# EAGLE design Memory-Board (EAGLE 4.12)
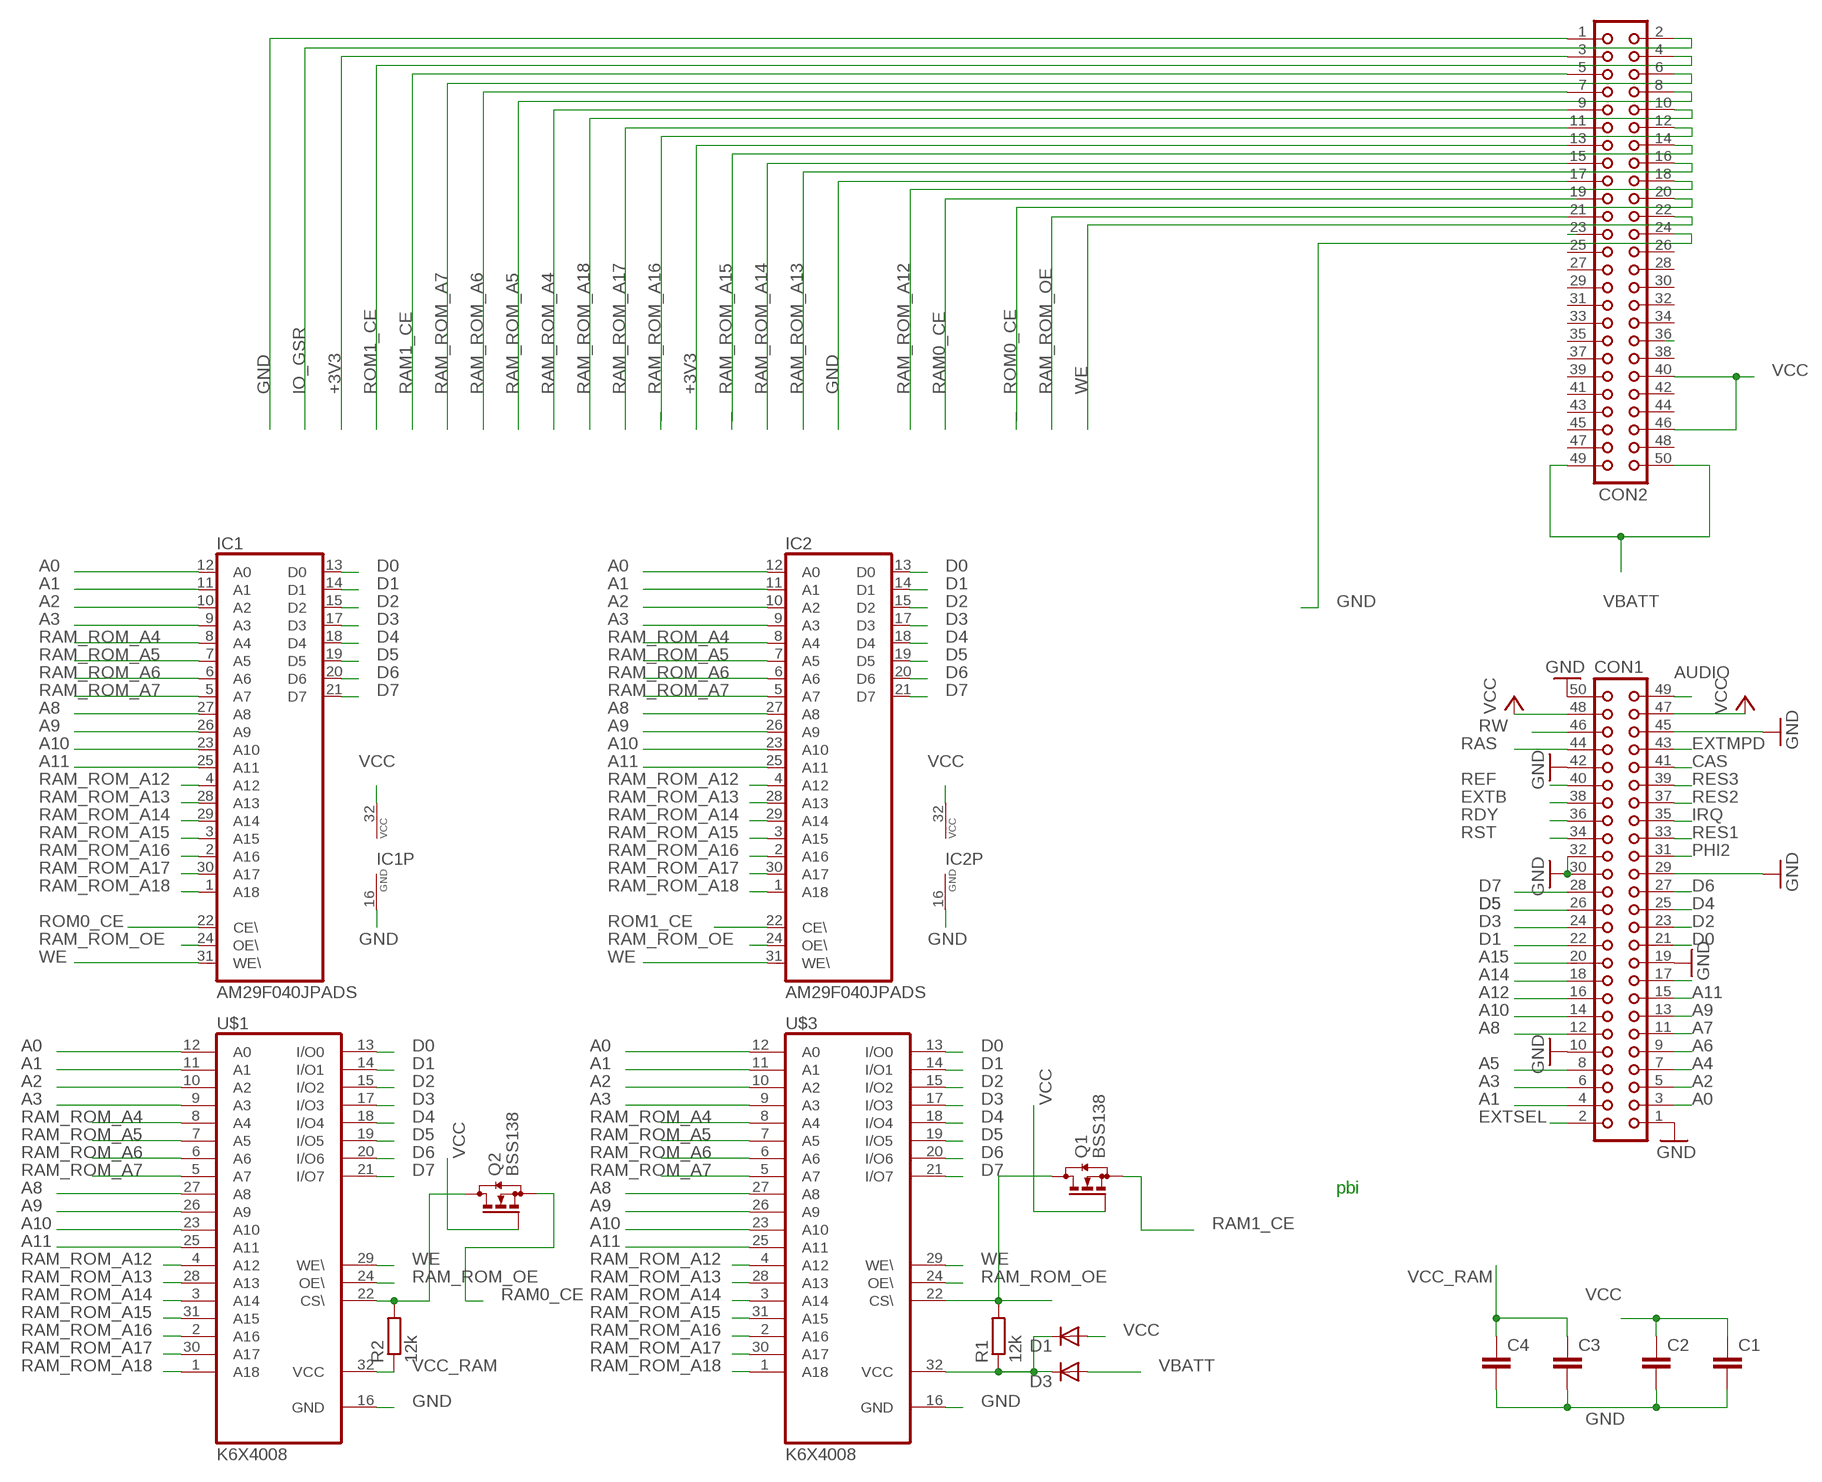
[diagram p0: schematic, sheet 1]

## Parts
C1  C-EUC1206  [C1206]
C2  C-EUC1206  [C1206]
C3  C-EUC1206  [C1206]
C4  C-EUC1206  [C1206]
CON1  CON50  [CON50]
CON2  CON50  [CON50]
D1  DIODE-DO214BA  [DO-214BA]
D3  DIODE-DO214BA  [DO-214BA]
IC1  AM29F040JPADS  [PLCC32R]
IC2  AM29F040JPADS  [PLCC32R]
Q1  BSS138  BSS123  [SOT23]
Q2  BSS138  BSS123  [SOT23]
R1  12k  R-EU_M0805  [M0805]
R2  12k  R-EU_M0805  [M0805]
U$1  K6X4008  [SOP32L]
U$3  K6X4008  [SOP32L]

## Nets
+3V3: CON2.3 CON2.13
A0: CON1.3 IC1.12(A0) IC2.12(A0) U$1.12(A0) U$3.12(A0)
A1: CON1.4 IC1.11(A1) IC2.11(A1) U$1.11(A1) U$3.11(A1)
A2: CON1.5 IC1.10(A2) IC2.10(A2) U$1.10(A2) U$3.10(A2)
A3: CON1.6 IC1.9(A3) IC2.9(A3) U$1.9(A3) U$3.9(A3)
A4: CON1.7
A5: CON1.8
A6: CON1.9
A7: CON1.11
A8: CON1.12 IC1.27(A8) IC2.27(A8) U$1.27(A8) U$3.27(A8)
A9: CON1.13 IC1.26(A9) IC2.26(A9) U$1.26(A9) U$3.26(A9)
A10: CON1.14 IC1.23(A10) IC2.23(A10) U$1.23(A10) U$3.23(A10)
A11: CON1.15 IC1.25(A11) IC2.25(A11) U$1.25(A11) U$3.25(A11)
A12: CON1.16
A13: CON1.17
A14: CON1.18
A15: CON1.20
AUDIO: CON1.49
CAS: CON1.41
D0: CON1.21 IC1.13(D0) IC2.13(D0) U$1.13(I/O0) U$3.13(I/O0)
D1: CON1.22 IC1.14(D1) IC2.14(D1) U$1.14(I/O1) U$3.14(I/O1)
D2: CON1.23 IC1.15(D2) IC2.15(D2) U$1.15(I/O2) U$3.15(I/O2)
D3: CON1.24 IC1.17(D3) IC2.17(D3) U$1.17(I/O3) U$3.17(I/O3)
D4: CON1.25 IC1.18(D4) IC2.18(D4) U$1.18(I/O4) U$3.18(I/O4)
D5: CON1.26 IC1.19(D5) IC2.19(D5) U$1.19(I/O5) U$3.19(I/O5)
D6: CON1.27 IC1.20(D6) IC2.20(D6) U$1.20(I/O6) U$3.20(I/O6)
D7: CON1.28 IC1.21(D7) IC2.21(D7) U$1.21(I/O7) U$3.21(I/O7)
DEBUG_LED8: CON2.36
EXTB: CON1.38
EXTMPD: CON1.43
EXTSEL: CON1.2
GND: C1.2 C2.2 C3.2 C4.2 CON1.1 CON1.10 CON1.19 CON1.29 CON1.30 CON1.32 CON1.42 CON1.45 CON1.50 CON2.1 CON2.17 CON2.24 IC1.16(GND) IC2.16(GND) U$1.16(GND) U$3.16(GND)
IO_GSR: CON2.2
IRQ: CON1.35
N$37: CON2.23
PHI2: CON1.31
RAM0_CE: CON2.19 Q2.2(S)
RAM0_CE1: Q2.3(D) R2.2 U$1.22(CS\)
RAM1_CE: CON2.5 Q1.2(S)
RAM1_CE1: Q1.3(D) R1.2 U$3.22(CS\)
RAM_ROM_A4: CON2.9 IC1.8(A4) IC2.8(A4) U$1.8(A4) U$3.8(A4)
RAM_ROM_A5: CON2.8 IC1.7(A5) IC2.7(A5) U$1.7(A5) U$3.7(A5)
RAM_ROM_A6: CON2.7 IC1.6(A6) IC2.6(A6) U$1.6(A6) U$3.6(A6)
RAM_ROM_A7: CON2.6 IC1.5(A7) IC2.5(A7) U$1.5(A7) U$3.5(A7)
RAM_ROM_A12: CON2.18 IC1.4(A12) IC2.4(A12) U$1.4(A12) U$3.4(A12)
RAM_ROM_A13: CON2.16 IC1.28(A13) IC2.28(A13) U$1.28(A13) U$3.28(A13)
RAM_ROM_A14: CON2.15 IC1.29(A14) IC2.29(A14) U$1.3(A14) U$3.3(A14)
RAM_ROM_A15: CON2.14 IC1.3(A15) IC2.3(A15) U$1.31(A15) U$3.31(A15)
RAM_ROM_A16: CON2.12 IC1.2(A16) IC2.2(A16) U$1.2(A16) U$3.2(A16)
RAM_ROM_A17: CON2.11 IC1.30(A17) IC2.30(A17) U$1.30(A17) U$3.30(A17)
RAM_ROM_A18: CON2.10 IC1.1(A18) IC2.1(A18) U$1.1(A18) U$3.1(A18)
RAM_ROM_OE: CON2.21 IC1.24(OE\) IC2.24(OE\) U$1.24(OE\) U$3.24(OE\)
RAS: CON1.44
RDY: CON1.36
REF: CON1.40
RES1: CON1.33
RES2: CON1.37
RES3: CON1.39
ROM0_CE: CON2.20 IC1.22(CE\)
ROM1_CE: CON2.4 IC2.22(CE\)
RST: CON1.34
RW: CON1.46
VBATT: CON2.49 CON2.50 D3.A
VCC: C1.1 C2.1 CON1.47 CON1.48 CON2.40 CON2.46 D1.A IC1.32(VCC) IC2.32(VCC) Q1.1(G) Q2.1(G)
VCC_RAM: C3.1 C4.1 D1.C D3.C R1.1 R2.1 U$1.32(VCC) U$3.32(VCC)
WE: CON2.22 IC1.31(WE\) IC2.31(WE\) U$1.29(WE\) U$3.29(WE\)
Unconnected: CON2.25 CON2.26 CON2.27 CON2.28 CON2.29 CON2.30 CON2.31 CON2.32 CON2.33 CON2.34 CON2.35 CON2.37 CON2.38 CON2.39 CON2.41 CON2.42 CON2.43 CON2.44 CON2.45 CON2.47 CON2.48

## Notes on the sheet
- pbi

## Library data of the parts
C1-C4 = rcl:C-EU: CAPACITOR, European symbol
CON1 CON2 = con-harting:CON50: CONNECTOR
D1 D3 = diode:DIODE-: DIODE
IC1 IC2 = am29-memory:AM29F040J: 4-Megabit FLASH MEMORY (512 K x 8 bit) 5 V-only
Q1 Q2 = transistor-small-signal:BSS123: N-CHANNEL MOS FET
R1 R2 = rcl:R-EU_: RESISTOR, European symbol
U$1 U$3 = memory:K6X4008

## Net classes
2 3.3: width 0.508 mm, drill 0.254 mm

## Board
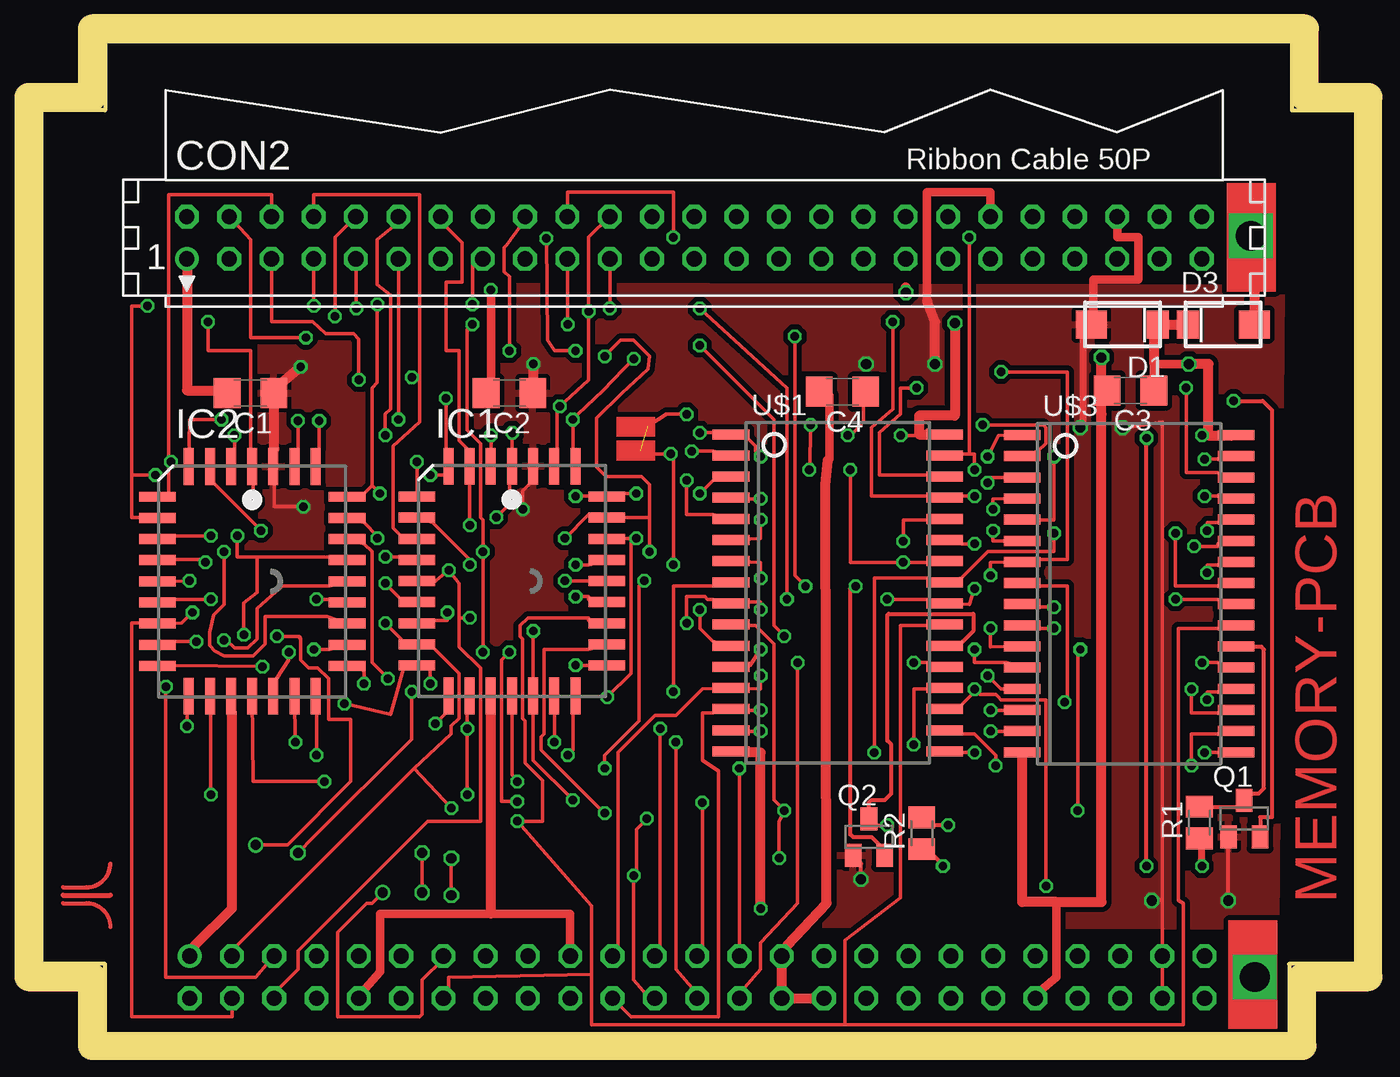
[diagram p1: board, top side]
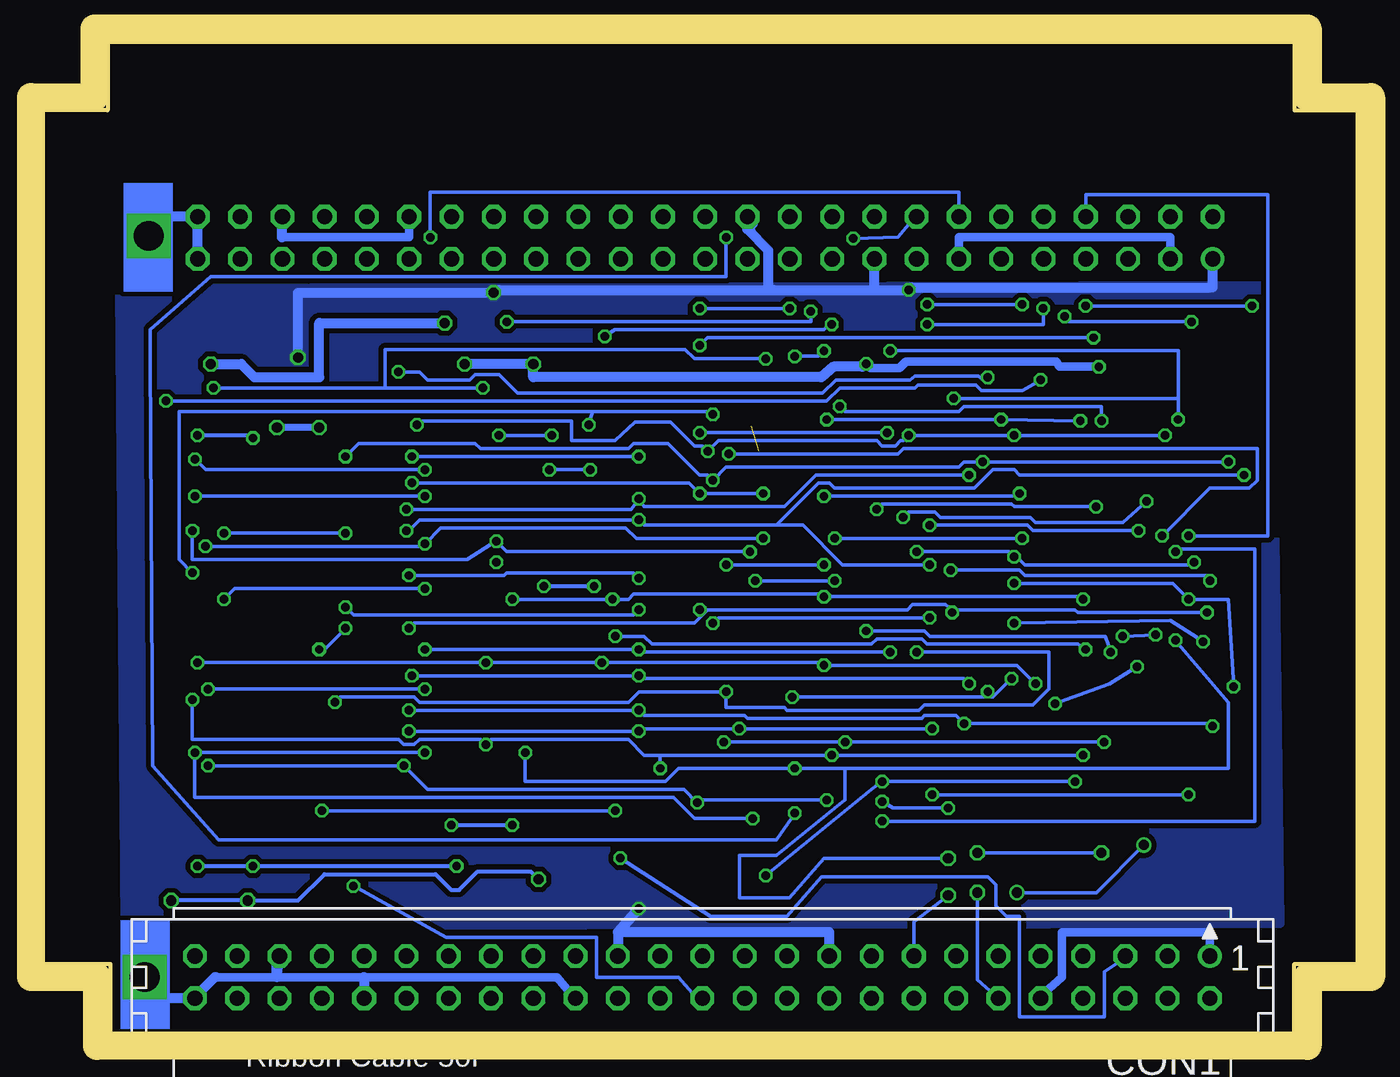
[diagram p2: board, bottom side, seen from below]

Size 79.06 x 59.69 mm. Coordinates in mm from the lower left corner, seen from the top.
Outline: 75.09,59.69 75.09,59.69
Outline: 75.09,59.69 3.81,59.69 3.81,55.56 0,55.56 0,4.29 3.81,4.29 3.81,0 74.93,0 74.93,4.29 79.06,4.29 79.06,55.56 75.09,55.56 75.09,59.69
Copper layers (1*16): Top 0.035mm / dielectric 1.5mm / Bottom 0.035mm
Design rules "ITead_rule": minimum track width 6mil, minimum drill 12mil, track to track 6mil, track to pad 6mil, pad to pad 6mil, via to via 6mil, smd to smd 0mil, copper to edge 10mil, drill to drill 10mil, minimum pad ring 10mil, minimum via ring 6mil, stop-mask expansion 2mil, vias tented up to drill 100mil, thermal gap 10mil
Milling: 15 lines

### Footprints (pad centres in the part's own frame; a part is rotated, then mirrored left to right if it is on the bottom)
C1206 = smd 1.6 x 1.8: 1 -1.4,0; 2 1.4,0
CON50 = drill 0.914 round: 1 -30.48,-1.27 | drill 0.914 octagon: 2 -30.48,1.27; 3 -27.94,-1.27; 4 -27.94,1.27; 5 -25.4,-1.27; 6 -25.4,1.27; 7 -22.86,-1.27; 8 -22.86,1.27; 9 -20.32,-1.27; 10 -20.32,1.27; 11 -17.78,-1.27; 12 -17.78,1.27; 13 -15.24,-1.27; 14 -15.24,1.27; 15 -12.7,-1.27; 16 -12.7,1.27; 17 -10.16,-1.27; 18 -10.16,1.27; 19 -7.62,-1.27; 20 -7.62,1.27; 21 -5.08,-1.27; 22 -5.08,1.27; 23 -2.54,-1.27; 24 -2.54,1.27; 25 0,-1.27; 26 0,1.27; 27 2.54,-1.27; 28 2.54,1.27; 29 5.08,-1.27; 30 5.08,1.27; 31 7.62,-1.27; 32 7.62,1.27; 33 10.16,-1.27; 34 10.16,1.27; 35 12.7,-1.27; 36 12.7,1.27; 37 15.24,-1.27; 38 15.24,1.27; 39 17.78,-1.27; 40 17.78,1.27; 41 20.32,-1.27; 42 20.32,1.27; 43 22.86,-1.27; 44 22.86,1.27; 45 25.4,-1.27; 46 25.4,1.27; 47 27.94,-1.27; 48 27.94,1.27; 49 30.48,-1.27; 50 30.48,1.27
DO-214BA = smd 1.85 x 1.68: A 1.87,0 | smd 1.32 x 1.68: C -2.12,0
PLCC32R = smd 0.6 x 2.2: 1 0,6.9; 2 -1.27,6.9; 3 -2.54,6.9; 4 -3.81,6.9; 14 -3.81,-6.9; 15 -2.54,-6.9; 16 -1.27,-6.9; 17 0,-6.9; 18 1.27,-6.9; 19 2.54,-6.9; 20 3.81,-6.9; 30 3.81,6.9; 31 2.54,6.9; 32 1.27,6.9 | smd 2.2 x 0.6: 5 -5.7,5.08; 6 -5.7,3.81; 7 -5.7,2.54; 8 -5.7,1.27; 9 -5.7,0; 10 -5.7,-1.27; 11 -5.7,-2.54; 12 -5.7,-3.81; 13 -5.7,-5.08; 21 5.7,-5.08; 22 5.7,-3.81; 23 5.7,-2.54; 24 5.7,-1.27; 25 5.7,0; 26 5.7,1.27; 27 5.7,2.54; 28 5.7,3.81; 29 5.7,5.08
SOT23 = smd 1 x 1.4: 1 -0.95,-1.1; 2 0.95,-1.1; 3 0,1.1
M0805 = smd 1.3 x 1.6: 1 -0.95,0; 2 0.95,0
SOP32L = smd 0.6 x 2.2: 1 -9.525,-6.416; 2 -8.255,-6.416; 3 -6.985,-6.416; 4 -5.715,-6.416; 5 -4.445,-6.416; 6 -3.175,-6.416; 7 -1.905,-6.416; 8 -0.635,-6.416; 9 0.635,-6.416; 10 1.905,-6.416; 11 3.175,-6.416; 12 4.445,-6.416; 13 5.715,-6.416; 14 6.985,-6.416; 15 8.255,-6.416; 16 9.525,-6.416; 17 9.525,6.416; 18 8.255,6.416; 19 6.985,6.416; 20 5.715,6.416; 21 4.445,6.416; 22 3.175,6.416; 23 1.905,6.416; 24 0.635,6.416; 25 -0.635,6.416; 26 -1.905,6.416; 27 -3.175,6.416; 28 -4.445,6.416; 29 -5.715,6.416; 30 -6.985,6.416; 31 -8.255,6.416; 32 -9.525,6.416

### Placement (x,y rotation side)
C1  12.54,38.58 180 top
C2  28.1,38.58 180 top
C3  65.41,38.73 180 top
C4  48.1,38.66 180 top
CON1  39.37,3.49 180 bottom
CON2  39.2,47.9 0 top
D1  64.93,42.7 180 top
D3  70.96,42.7 0 top
IC1  28.24,27.29 0 top
IC2  12.65,27.27 0 top
Q1  72.23,13.02 0 top
Q2  49.69,11.91 0 top
R1  69.53,12.78 90 top
R2  52.86,12.14 90 top
U$1  47.82,26.58 270 top
U$3  65.32,26.53 270 top

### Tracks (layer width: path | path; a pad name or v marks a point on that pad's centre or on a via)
+3V3
  Bottom 0.203: CON2.3 11.27,46.35 | 23.97,46.35 CON2.13
  Bottom 0.508: 11.27,46.35 11.27,47.94 23.97,47.94 23.97,46.35
A0  (via drill 0.51)
  Top 0.203: v56.04,23.18 56.04,22.38 57.94,22.38 U$3.12 | v43.18,23.18 42.55,22.22 U$1.12 | v9.29,23.65 7.94,23.65 IC2.12 | v20.64,24.76 21.59,23.81 21.59,23.65 IC1.12 23.5,23.34 25.08,21.75 25.08,19.05 24.61,18.57 24.61,18.1 22.38,16.03 | 22.38,16.03 11.75,5.4 CON1.3 | v28.1,23.02 27.62,22.54 27.62,15.72 27.62,15.56 27.62,14.05 v28.57,14.05 | 22.38,16.03 v24.61,13.65
  Bottom 0.203: v56.04,23.18 v43.18,23.18 42.86,23.02 v28.1,23.02 | v9.29,23.65 11.27,24.92 v20.64,24.76 | v28.57,14.05 27.94,13.65 v24.61,13.65
A1  (via drill 0.51)
  Top 0.203: CON1.4 11.43,1.9 11.43,1.11 5.4,1.11 5.4,24.76 5.87,24.76 IC2.11 8.41,24.76 v9.05,25.4 | v24.37,25.4 24.37,24.92 23.5,24.92 IC1.11 | v56.99,24.45 56.99,23.34 U$3.11 | v39.53,25.56 39.53,24.45 40.32,23.65 U$1.11
  Bottom 0.203: v9.05,25.4 16.83,25.4 16.99,25.56 24.13,25.56 v24.37,25.4 24.61,25.72 24.77,25.88 26.75,25.88 27.07,25.56 39.05,25.56 39.21,25.4 | v56.99,24.45 56.67,24.76 39.85,24.76 39.21,25.4 | v39.53,25.56 39.37,25.4 39.21,25.4
A2  (via drill 0.51)
  Top 0.203: v60.8,24.45 59.85,24.45 U$3.10 | v62.39,23.18 62.23,23.02 v62.23,13.49 | U$1.10 42.39,24.61 42.86,24.61 43.97,23.49 43.97,14.13 v44.61,13.49 44.29,12.86 v44.29,10.64 | v10.16,26.19 7.94,26.19 IC2.10 | v20.64,27.15 21.59,26.19 IC1.10 | v7.46,20.95 7.46,3.49 12.86,3.49 13.65,4.44 13.34,4.44 CON1.5
  Bottom 0.2: 22.22,9.52 32.23,9.52 34.29,7.14 38.89,7.14
  Bottom 0.203: v60.8,24.45 62.07,23.18 v62.39,23.18 | v44.61,13.49 v62.23,13.49 | v20.64,27.15 11.11,27.15 v10.16,26.19 7.78,26.19 v7.46,20.95 | 38.89,7.14 v44.29,10.64 | CON1.5 14.29,4.44 15.24,3.81 15.24,1.11 16.19,1.11 20.32,1.11 20.32,7.14 21.11,7.14 21.75,7.78 21.75,9.05 22.22,9.52
A3  (via drill 0.51)
  Top 0.203: v60.8,25.72 59.85,25.72 U$3.9 | v43.18,25.56 43.18,26.03 42.39,26.03 U$1.9 40.32,26.19 40.01,26.19 39.85,26.35 38.74,26.35 v38.74,24.76 | v8.89,27.3 IC2.9 | IC1.9 23.5,27.15 v24.45,27.94 25.08,27.15 25.08,25.08 | 25.08,25.08 25.08,23.34 26.35,22.07 26.35,12.86 23.18,12.86 15.4,5.08 15.4,3.97 14.29,2.86 CON1.6 | 25.08,25.08 v25.72,25.08
  Bottom 0.203: v60.8,25.72 60.33,25.24 43.5,25.24 v43.18,25.56 | v8.89,27.3 8.73,27.62 20,27.62 20.32,27.94 v24.45,27.94 | v38.74,24.76 38.42,25.08 v25.72,25.08
A8  (via drill 0.5, 0.51, 0.61)
  Top 0.2: v22.22,20.64 22.22,17.78 16.35,11.91 v15.4,10.95 | v22.86,8.57 v22.86,10.95
  Top 0.203: v56.04,29.53 55.25,29.53 U$1.27 | v69.22,29.37 70.64,29.37 70.64,29.53 U$3.27 | v20.8,21.43 19.84,22.38 19.84,29.05 19.37,29.53 IC2.27 | v33.97,20.32 35.4,21.75 35.4,29.84 34.93,29.84 | 34.93,29.84 v35.72,29.84 | 34.93,29.84 IC1.27
  Bottom 0.2: v22.22,20.64 21.91,20.32 | v22.86,10.95 v15.4,10.95 | v22.86,8.57 22.86,3.33 CON1.12 | CON1.12
  Bottom 0.203: v69.22,29.37 56.2,29.37 v56.04,29.53 55.09,30.48 43.97,30.48 43.34,29.84 v35.72,29.84 | v20.8,21.43 21.91,20.32 v33.97,20.32
A9  (via drill 0.51, 0.61)  (1 unrouted)
  Top 0.2: IC2.26 17.15,28.73
  Top 0.203: 12.94,28.73 11.75,28.73 v11.75,30 | 12.94,28.73 16.99,28.73 IC2.26 | v32.07,28.26 32.86,28.26 IC1.26 | v37.94,28.26 37.94,34.61 v37.78,34.92 36.67,34.92 35.96,35.08 | U$1.26 53.18,28.42 v51.75,28.42 48.58,28.42 v48.58,33.97 | v70.01,27.78 70.01,28.26 70.64,28.26 U$3.26 | CON1.13 24.13,4.6 22.86,3.33 22.86,1.27 22.7,1.11 17.78,1.11 17.78,6.19 19.53,7.94 19.84,7.94 v20.48,8.57 | v12.86,11.43 14.76,11.43 18.57,15.24 18.57,18.97 17.22,18.97 17.22,21.43 16.59,22.07 16.03,22.07 15.56,22.54 15.56,23.81 15.48,23.97 v14.13,23.97 | v12.14,24.05 12.14,25.96 12.94,26.59 12.94,28.73 | v38.74,37.31 37.54,37.31 36.43,36.59 | v46.2,36.67 v46.12,33.97
  Bottom 0.203: v11.75,30 8.89,32.86 6.51,32.86 6.03,33.34 6.03,35.24 27.31,35.24 27.62,34.92 v37.78,34.92 | v32.07,28.26 v37.94,28.26 38.26,28.42 | v70.01,27.78 70.8,28.57 70.8,37.46 45.96,37.46 | 45.96,37.46 38.89,37.46 v38.74,37.31 | v20.48,8.57 15.72,8.57 v12.86,11.43 | v14.13,23.97 v12.14,24.05 | v46.12,33.97 v48.58,33.97 | 45.96,37.46 v46.2,36.67
A10  (via drill 0.51)
  Top 0.203: IC2.23 17.15,25.16 13.41,25.16 13.41,23.49 12.7,22.78 10.95,22.78 10.4,23.1 10.08,23.42 10.08,24.21 10.32,25.24 10.95,25.88 v10.95,29.05 | IC1.23 32.86,24.92 32.86,25.08 29.21,25.08 28.73,24.61 28.73,23.97 28.89,23.81 28.89,19.05 29.05,18.89 29.05,16.35 30.08,15.32 30.08,12.86 v28.57,12.86 33.02,7.78 33.02,3.65 | 48.26,0.63 48.26,5.71 51.59,8.25 51.59,24.61 53.18,24.61 U$1.23 | 48.26,0.63 33.02,0.63 33.02,3.65 | 48.26,0.63 68.58,0.63 68.58,7.94 68.26,8.1 68.26,24.45 70.64,24.45 U$3.23 | 48.26,0.63 47.31,0.63 | 33.02,3.65 24.45,3.49 24.45,2.06 CON1.14
  Bottom 0.203: v10.95,29.05 10.8,29.21 6.19,29.21 6.19,12.86 v28.57,12.86
A11  (via drill 0.51, 0.61)
  Top 0.2: v24.61,10.64 v24.61,8.41
  Top 0.203: v68.1,30.16 68.1,26.99 70.64,26.99 U$3.25 | v60.8,30.16 60.8,29.05 60.17,29.05 56.83,29.05 55.25,27.46 U$1.25 53.18,27.46 50.48,27.46 50.01,27.46 v50.01,16.99 | IC2.25 17.3,26.99 14.37,26.99 14.37,26.91 12.94,25.64 12.94,23.81 12.38,23.26 11.59,23.26 11.11,23.73 v10.95,23.73 | v31.43,27.3 32.86,27.3 IC1.25 | v36.2,27.3 35.88,26.99 35.88,18.89 33.81,16.83 v33.81,16.03
  Bottom 0.2: v33.81,16.03 30.8,16.03 30.8,14.13 34.92,10.79 37.15,10.79 37.15,8.25 34.13,8.25 32.07,10.64 v24.61,10.64 24.45,10.64 | v24.61,8.41 26.67,6.83 CON1.15
  Bottom 0.203: v60.8,30.16 v68.1,30.16 | v10.95,23.73 7.78,20 7.78,16.03 v33.81,16.03 40.8,16.03 41.59,15.24 50.01,15.24 v50.01,16.99 | v36.2,27.3 v31.43,27.3
D0  (via drill 0.51)
  Top 0.203: v13.26,22.15 7.94,22.22 IC2.13 | v18.18,19.92 20.95,19.29 21.27,20.32 21.75,22.07 IC1.13 23.34,22.07 v23.34,21.11 | v56.83,21.59 57.63,20.8 U$3.13 | v56.83,21.59 | v43.18,21.59 43.18,20.8 U$1.13 39.69,20.8 38.1,19.21 36.83,19.21 34.61,16.99 34.61,5.4 CON1.21
  Bottom 0.203: v13.26,22.15 14.92,21.11 v18.18,19.92 | v56.83,21.59 v43.18,21.59 42.86,21.43 23.65,21.43 v23.34,21.11
D1  (via drill 0.51)
  Top 0.203: v8.73,18.57 8.73,19.53 IC2.14 | v23.65,18.73 24.29,19.37 IC1.14 | v56.99,19.53 57.94,19.53 U$3.14 | v43.18,19.53 42.39,19.53 U$1.14 40.32,19.37 39.69,19.37 39.69,16.51 40.64,15.87 40.64,1.11 35.4,1.11 34.61,1.9 34.61,2.06 CON1.22
  Bottom 0.203: v8.73,18.57 8.89,18.73 v23.65,18.73 23.97,19.05 24.13,19.21 26.04,19.21 26.19,19.05 36.67,19.05 36.83,19.21 42.86,19.21 v43.18,19.53 v56.99,19.53
D2  (via drill 0.51)
  Top 0.203: v10.16,14.45 10.16,19.37 IC2.15 | v25.56,14.45 v25.56,18.41 25.56,19.37 IC1.15 | v56.99,18.26 57.94,18.26 U$3.15 | v43.18,18.26 42.39,18.26 U$1.15 | v37.15,18.41 37.15,5.4 CON1.23
  Bottom 0.203: v10.16,14.45 v25.56,14.45 | v56.99,18.26 v43.18,18.26 42.86,18.41 v37.15,18.41 v25.56,18.41
D3  (via drill 0.51)
  Top 0.203: v56.04,16.99 55.25,16.99 U$1.17 | v69.85,16.99 70.64,16.99 U$3.17 | v16.99,15.24 12.7,15.24 IC2.17 | v28.58,15.24 28.26,15.64 IC1.17 | CON1.24 36.51,2.22 35.56,3.33 v35.56,9.6 35.72,9.68 35.72,12.38 v36.35,13.02
  Bottom 0.203: v56.04,16.99 v69.85,16.99 69.85,14.29 41.12,14.29 39.85,13.02 v36.35,13.02 | v16.99,15.24 v28.58,15.24 29.21,14.76 v35.56,9.6
D4  (via drill 0.51)
  Top 0.203: v14.84,23.02 14.84,22.54 14.13,21.43 IC2.18 | v29.53,24.29 29.53,21.43 IC1.18 29.53,19.37 29.53,16.51 v31.91,14.13 | v57.31,16.19 57.31,16.83 56.04,18.1 55.25,18.1 U$1.18 | v69.06,16.19 69.06,18.1 69.85,18.1 70.64,18.1 U$3.18 | v39.69,13.97 39.69,5.4 CON1.25
  Bottom 0.203: v14.84,23.02 15.16,23.97 25.72,23.97 26.04,24.29 v29.53,24.29 | v69.06,16.19 v57.31,16.19 56.99,15.87 55.88,14.76 40.48,14.76 v39.69,13.97 39.37,14.13 v31.91,14.13
D5  (via drill 0.51)
  Top 0.203: v69.06,20.8 69.06,19.37 69.69,19.37 70.64,19.37 U$3.19 | U$1.19 55.25,19.84 56.04,20.64 v56.04,20.8 56.36,20.48 57.31,20.48 57.47,20.32 57.63,20.16 60.33,20.16 v60.33,8.97 | v15.24,17.62 IC2.19 | v30.8,17.62 30.8,19.37 IC1.19 | v38.1,17.62 38.1,3.97 39.05,2.86 CON1.26
  Bottom 0.203: v56.04,20.8 v69.06,20.8 | v15.24,17.62 v30.8,17.62 v38.1,17.62 | v60.33,8.97 54.77,5.87 45.72,5.87 45.72,3.49 40.8,3.49 40.01,2.54 CON1.26
D6  (via drill 0.51)
  Top 0.203: v16.51,16.83 16.51,19.37 IC2.20 | v31.59,16.83 31.91,17.14 31.91,19.37 IC1.20 | v52.39,17.46 52.39,20.8 53.18,20.8 U$1.20 | v70.01,20.16 70.01,20.64 70.64,20.64 U$3.20 | v41.91,16.03 41.91,5.4 CON1.27
  Bottom 0.203: v16.51,16.83 v31.59,16.83 41.91,16.83 | 41.91,16.83 42.86,16.83 43.82,17.78 52.07,17.78 v52.39,17.46 52.71,17.78 56.36,17.78 56.67,17.46 57.31,17.46 57.63,17.78 70.01,17.78 v70.01,20.16 | 41.91,16.83 v41.91,16.03
D7  (via drill 0.51)
  Top 0.203: v19.37,21.11 19.37,21.91 IC2.21 | v32.07,22.22 32.86,22.22 IC1.21 | v52.39,22.38 53.18,22.38 U$1.21 | v69.69,22.38 70.64,22.38 U$3.21 | v45.4,22.38 45.4,7.94 43.18,5.56 43.18,3.97 42.23,2.86 CON1.28
  Bottom 0.203: v19.37,21.11 20.48,22.22 v32.07,22.22 32.39,22.38 v45.4,22.38 v52.39,22.38 v69.69,22.38
GND  (via drill 0.51, 0.61, 1.78 pad 0.51)
  Top 0.203: 10.48,38.73 C1.2 | CON2.1 8.73,46.04 | 26.99,39.37 C2.2 | 11.43,19.37 IC2.16 | 26.99,19.37 IC1.16 | CON1.10 19.21,2.54 | 58.9,16.83 U$3.16 | CON1.42 60.01,2.7 | 45.09,2.22 CON1.30 44.45,2.86 | 46.36,2.22 CON1.32 | 44.77,5.4 CON1.29 44.45,4.13 | 42.39,16.99 U$1.16
  Top 0.508: v26.99,44.77 26.99,39.37 | CON1.19 31.75,7.3 26.99,7.3 20.32,7.3 20.32,3.81 19.21,2.54 | 60.01,2.7 60.96,3.49 60.96,8.02 | C4.2 47.31,38.42 47.31,34.61 47.23,34.53
  Top 0.61: 10.48,38.73 8.73,38.73 8.73,46.04 | 11.43,19.37 11.43,7.62 9.21,5.4 CON1.1 | 26.99,7.3 26.99,19.37 | 58.9,16.83 58.9,8.02 60.96,8.02 63.66,8.02 63.66,37.31 | 45.09,2.22 46.36,2.22 | 47.23,34.53 47.07,33.1 47.15,7.94 44.77,5.4 | 42.39,16.99 43.18,16.99 v43.18,7.62 | 44.45,4.13 44.45,2.86 | v51.91,44.61 51.9,44.94 | 63.66,37.31 | 63.66,37.31 63.66,38.73 | 63.66,40.8 v63.66,40.72 63.66,38.73 | 63.66,38.73 C3.2
  Bottom 0.203: 29.05,44.77 CON2.17 | 36.04,47.62 36.35,48.58 CON2.24 | CON1.1 8.89,5.08 | 19.05,2.38 CON1.10 | 64.93,4.29 CON1.45 | 59.69,2.54 CON1.42 | CON1.32 47.31,2.54 | CON1.19 31.75,5.08
  Bottom 0.508: 8.89,5.08 8.89,6.19 16.83,6.19 17.78,6.19 17.78,3.49 19.05,2.38 | 68.58,3.49 64.93,3.49 59.69,3.49 48.1,3.49 47.31,2.54 | 68.66,3.49 69.85,2.3
  Bottom 0.61: 29.05,44.77 v26.99,44.77 26.83,44.93 8.89,44.93 8.72,44.94 CON2.1 | 64.93,4.29 64.93,3.49 CON1.45 | 44.45,6.19 CON1.29 | 59.69,3.49 59.69,2.54 | 31.75,5.08 31.75,6.19 44.45,6.19 | 44.45,6.19 v43.18,7.62 | v63.66,40.72 63.66,44.61 v51.91,44.61 51.59,44.77 35.4,44.77 | CON1.45 | CON2.17 29.05,46.63 29.05,44.77 | 29.05,44.77 | 29.05,44.77 35.08,44.77 35.4,44.77 | 36.67,49.05 36.35,48.74 | 36.67,49.05 36.67,48.42 35.4,47.15 35.4,44.77 | 35.4,44.77 | 36.67,49.05 36.67,49.21 36.66,49.2 CON2.24 | 69.85,2.3 CON1.50 | 68.58,3.49 68.66,3.49 | 68.66,3.49 | 68.66,3.49 69.93,2.22 71.44,2.22 72.47,3.25 72.87,3.25 73.1,3.49 v72.87,3.49
  pour Bottom (isolate 0.305): 5.24,45.09 74.45,44.93 74.14,6.51 4.6,6.67 5.08,43.97
N$34
  Top 0.305: 1.27,8.41 4.13,8.41
N$35
  Top 0.254: 1.27,8.89 2.7,8.89 arc90 4.13,10.32
N$36
  Top 0.254: 1.27,7.94 2.7,7.94 arc-90 4.13,6.51
RAM0_CE  (via drill 0.51, 0.51 pad 0.51)
  Top 0.203: v45.88,26.99 45.24,27.62 v45.24,41.99 | CON2.19 31.59,46.63 v31.59,42.7
  Top 0.254: v48.89,26.99 48.58,26.83 48.58,12.06 48.74,11.91 49.85,11.91 50.64,11.11 Q2.2
  Bottom 0.203: v45.24,41.99 44.61,42.39 32.07,42.39 31.75,42.7 v31.59,42.7
  Bottom 0.254: v45.88,26.99 45.8,26.99 v48.89,26.99
RAM0_CE1  (via drill 0.51 pad 0.51)
  Top 0.254: U$1.22 55.07,23.4 55.96,24.29 55.96,25.32 50.88,25.32 50.8,25.24 50.8,17.7 51.04,17.46 51.04,14.53 50.64,14.13 49.85,14.13 49.69,13.97 49.69,13.02 | R2.2 52.86,12.86 52.86,12.62 v54.45,12.62 | Q2.3 49.69,13.02 | v50.8,12.62 50.09,12.62 49.69,13.02
  Bottom 0.254: v50.8,12.62 v54.45,12.62
RAM1_CE  (via drill 0.51)
  Top 0.203: CON2.5 13.81,46.51 13.81,42.86 16.27,42.86 17.07,42.15 18.73,42.15 19.05,41.83 19.05,39.45 18.97,39.37 v19.05,39.37
  Top 0.254: v71.6,38.1 73.34,38.1 73.9,37.54 73.9,13.1 73.26,13.1 73.18,13.1 Q1.2 | Q1.2 | Q1.2
  Bottom 0.203: v71.6,38.1 31.91,38.1 31.12,38.89 26.59,38.89 26.43,39.05 22.94,39.05 22.62,38.74 20.16,38.74 v19.05,39.37
RAM1_CE1
  Top 0.254: 73.42,14.84 73.16,14.58 | 73.42,14.84 73.42,23.18 73.26,23.34 71.76,23.34 U$3.22 | 73.42,14.84 73.1,14.53 72.23,14.53 72.23,14.13 | 72.23,14.13 Q1.3 | R1.2 72.23,13.73 72.23,14.13
RAM_ROM_A4  (via drill 0.51)
  Top 0.203: v61.44,20 61.6,20.16 61.6,26.99 59.85,26.99 U$3.8 | v37.94,20.64 37.94,26.99 38.74,26.99 40.32,26.99 U$1.8 | v9.84,28.42 10,28.57 8.41,28.57 7.94,28.57 IC2.8 | v20.64,28.73 21.59,28.73 IC1.8 | v18.89,43.66 18.89,46.04 CON2.9 | v25.88,42.7 25.56,42.39 25.56,36.35 26.35,35.56 26.35,31.11 26.51,30.96 v26.51,29.05 v26.51,23.02
  Bottom 0.203: v61.44,20 61.12,20.32 56.67,20.32 56.36,20 43.82,20 43.18,20.64 v37.94,20.64 37.94,19.68 34.45,19.68 34.29,19.53 26.35,19.53 26.04,19.84 19.53,19.84 18.57,20.8 18.57,23.02 v26.51,23.02 | v9.84,28.42 10.16,28.26 20,28.26 20.48,28.73 v20.64,28.73 20.96,29.05 v26.51,29.05 | v18.89,43.66 18.89,42.7 v25.88,42.7
RAM_ROM_A5  (via drill 0.51)
  Top 0.203: v43.18,27.46 43.18,28.42 U$1.7 | v56.99,27.62 56.99,28.42 U$3.7 59.85,28.57 61.6,28.57 61.6,39.85 v57.63,39.85 | v10.16,30 7.94,30 IC2.7 | 22.7,39.53 22.7,36.83 21.11,35.4 21.11,30.48 21.59,30 IC1.7 | 22.7,39.53 22.7,50.48 16.35,50.48 16.35,49.85 CON2.8 | 22.7,39.53 v22.23,39.53
  Bottom 0.203: v43.18,27.46 43.5,27.78 51.12,27.78 51.28,27.62 v56.99,27.62 | v10.16,30 5.4,30 5.4,50.48 16.35,50.48 16.35,49.37 CON2.8 | 57.47,39.69 v57.63,39.85 56.36,39.85 55.88,39.37 53.34,39.37 53.02,39.69 51.59,39.69 50.48,38.58 32.15,38.58 31.35,39.37 26.91,39.37 26.59,39.61 22.78,39.61 22.62,39.45 v22.23,39.53
RAM_ROM_A6  (via drill 0.51)
  Top 0.203: 5.4,33.65 5.4,43.81 v6.35,43.81 | 5.4,33.65 5.4,31.11 5.87,31.11 IC2.6 | v43.18,30.96 43.18,29.84 U$1.6 | v57.15,30.32 57.15,29.69 57.94,29.69 U$3.6 | v25.72,28.26 25.72,28.57 23.5,30.8 IC1.6 | 5.4,33.65 v6.83,33.65 | CON2.7 16.34,43.98 v16.35,43.81
  Bottom 0.203: v57.15,30.32 56.99,30.32 56.36,30.96 43.34,30.96 v43.18,30.96 42.86,30.64 34.93,30.64 | v25.72,28.26 30.96,28.26 33.34,30.64 34.93,30.64 | v6.83,33.65 20.32,33.65 20.64,33.97 21.91,33.97 23.02,32.86 31.43,32.86 31.75,33.18 32.39,33.18 34.93,30.64 | v6.35,43.81 v16.35,43.81
RAM_ROM_A7  (via drill 0.51)
  Top 0.203: 7.62,34.45 7.62,32.54 IC2.5 | 7.62,34.45 7.62,50.48 13.81,50.48 13.81,49.69 CON2.6 | v38.74,33.34 38.74,31.27 40.32,31.27 U$1.5 | v22.54,34.45 22.54,32.54 IC1.5 | v60.8,34.77 60.8,30.96 59.85,30.96 U$3.5 | 7.62,34.45 v7.78,34.45
  Bottom 0.203: v60.8,34.77 60.01,35.56 53.02,35.56 52.71,35.24 43.82,35.24 43.5,35.56 41.43,35.56 39.53,33.65 39.05,33.65 v38.74,33.34 37.94,34.13 23.97,34.13 23.65,34.45 v22.54,34.45 v7.78,34.45
RAM_ROM_A12  (via drill 0.51)
  Top 0.203: v43.18,32.23 42.39,32.23 U$1.4 | v57.15,31.59 57.15,32.23 U$3.4 | v10.8,36.99 8.89,36.99 IC2.4 | v24.29,38.26 24.29,35.24 IC1.4 24.29,33.65 v23.34,33.65 | CON2.18 28.73,48.58 27.94,47.47 27.78,47.31 27.78,45.88 28.1,45.56 v28.1,41.12
  Bottom 0.203: v57.15,31.59 43.66,31.59 v43.18,32.23 42.86,31.75 34.45,31.75 32.54,33.65 v23.34,33.65 | v10.8,36.99 10.8,38.26 | 10.8,38.26 v24.29,38.26 | v28.1,41.12 10.8,41.12 10.8,38.26
RAM_ROM_A13  (via drill 0.51)
  Top 0.203: v20.16,29.84 20.16,30 19.37,30.8 IC2.28 | v31.43,29.84 32.86,31.27 IC1.28 34.93,31.11 36.51,31.11 | v51.75,29.69 51.75,30.96 53.18,30.96 U$1.28 | 36.51,31.11 v36.51,29.05 | v70.01,30.32 70.01,30.8 70.64,30.8 U$3.28 | 36.51,40.8 35.56,41.75 34.77,41.75 v33.81,40.8 | 30.56,47.78 v30.32,47.86 30.4,41.75 30.8,41.12 v32.07,41.12 | 36.51,31.11 36.51,33.1 36.04,33.58 33.89,33.58 33.34,34.13 33.34,37.07 34.85,38.58 36.43,40 36.51,40.8 | 36.51,40.8
  Bottom 0.203: v20.16,29.84 v31.43,29.84 | v36.51,29.05 51.12,29.05 v51.75,29.69 53.5,28.57 70.01,28.57 v70.01,30.32 | CON2.16 26.83,48.89 27.62,47.94 v30.32,47.86 30.48,47.94 | v33.81,40.8 32.38,40.8 31.91,41.12 v32.07,41.12
RAM_ROM_A14  (via drill 0.51)
  Top 0.203: 19.84,33.02 19.37,32.54 IC2.29 | 19.84,33.02 19.84,38.89 20.16,39.21 v20.16,43.89 | v25.88,43.89 25.88,46.51 CON2.15 | v35.72,32.54 34.93,32.54 IC1.29 32.86,32.38 v32.07,32.38 | v39.53,32.54 40.32,33.34 U$1.3 | v56.83,33.18 56.83,33.5 57.94,33.5 U$3.3 | 19.84,33.02 v20.32,32.54
  Bottom 0.203: v20.16,43.89 v25.88,43.89 | v35.72,32.54 v39.53,32.54 40.16,33.18 v56.83,33.18 | v20.32,32.54 20.48,32.38 v32.07,32.38
RAM_ROM_A15  (via drill 0.51)
  Top 0.203: 55.25,34.92 56.04,34.92 v56.04,33.97 | v69.85,34.61 70.64,34.61 U$3.31 | 55.25,34.92 U$1.31 55.25,34.92 | v13.18,30.32 10.32,33.18 IC2.3 | v25.72,30.64 25.72,33.18 IC1.3 25.56,35.24 25.08,35.72 | 25.24,47.62 24.29,48.58 CON2.14 | 55.25,34.92 55.72,34.92 v55.72,47.94 | 25.24,47.62 | 25.24,47.62 25.24,45.24 24.29,45.24 24.29,41.12 25.08,41.12 25.08,35.72 | 25.08,35.72
  Bottom 0.203: v56.04,33.97 69.22,33.97 v69.85,34.61 | v13.18,30.32 19.53,30.32 19.84,30.64 v25.72,30.64 | v55.72,47.94 55.72,50.64 23.97,50.64 23.97,49.37 CON2.14
RAM_ROM_A16  (via drill 0.51)
  Top 0.203: v11.59,36.04 11.59,35.24 IC2.2 | v26.99,36.04 26.99,35.24 IC1.2 | v39.05,35.08 40.32,35.08 U$1.2 | v56.52,36.67 60.17,36.67 60.33,36.51 60.33,35.56 59.85,35.08 U$3.2 | v20.64,36.04 20.64,37.31 20.96,37.62 20.96,44.45 20.16,45.08 20.16,47.78 21.11,48.58 CON2.12
  Bottom 0.203: v11.59,36.04 v20.64,36.04 v26.99,36.04 27.31,35.72 27.46,35.72 27.78,35.4 28.58,35.4 28.89,35.72 38.42,35.72 v39.05,35.08 39.37,35.4 39.85,35.4 41.28,36.83 43.42,36.83 44.61,35.72 47.23,35.72 47.23,36.12 47.23,36.91 47.7,36.91 56.28,36.91 v56.52,36.67 | v56.52,36.67 56.36,36.83 | v56.52,36.67
RAM_ROM_A17  (via drill 0.51)
  Top 0.203: v68.74,38.89 68.74,33.81 70.64,33.81 U$3.30 | v52.55,38.89 51.59,38.89 51.59,37.31 50.32,36.19 50.32,33.65 53.18,33.65 U$1.30 | v16.67,36.91 16.67,35.24 IC2.30 | v21.43,36.99 21.43,46.04 CON2.11 | IC1.30 31.91,35.24 v31.91,36.99 32.23,37.31 33.73,38.73 v35.56,40.64
  Bottom 0.203: 58.42,38.89 v52.55,38.89 | 58.42,38.89 v68.74,38.89 | v16.67,36.91 v21.43,36.99 v31.91,36.99 | 58.42,38.89 58.42,41.2 40.4,41.2 39.85,40.64 v35.56,40.64
RAM_ROM_A18  (via drill 0.51)
  Top 0.203: v10,42.86 10,41.12 12.54,41.12 12.54,35.4 IC2.1 12.7,33.18 v12.7,32.07 | v28.26,36.19 28.26,35.24 IC1.1 28.1,33.18 28.1,31.91 v27.31,31.11 | v39.53,36.19 40.32,36.19 U$1.1 42.39,35.88 42.86,35.4 42.86,35.08 v43.18,34.77 | v56.83,34.77 57.47,36.04 U$3.1 | 18.88,49.2 18.89,49.21 | 18.88,49.2 CON2.10 | v17.62,43.18 17.62,47.94 18.88,49.2
  Bottom 0.203: v28.26,36.19 v39.53,36.19 | v43.18,34.77 v56.83,34.77 | v12.7,32.07 14.13,30.8 19.37,30.8 19.69,31.11 25.08,31.11 25.4,31.43 26.99,31.43 v27.31,31.11 | v10,42.86 17.62,42.86 v17.62,43.18
RAM_ROM_OE  (via drill 0.51)
  Top 0.203: v16.51,26.19 17.3,26.19 IC2.24 | v32.07,26.35 32.86,26.35 32.86,26.19 IC1.24 | v50.8,26.19 53.18,26.19 U$1.24 55.72,25.88 v56.04,26.83 | v68.1,26.19 70.64,26.19 U$3.24 | v39.53,43.66 44.77,38.89 v44.77,26.19 | 34.13,46.63 34.13,46.67 | 34.13,46.63 CON2.21 | v34.13,43.66 34.13,46.63
  Bottom 0.203: v16.51,26.19 16.67,26.35 v32.07,26.35 32.39,26.51 43.5,26.51 43.82,26.19 v44.77,26.19 v50.8,26.19 | v68.1,26.19 67.47,26.83 v56.04,26.83 | v39.53,43.66 v34.13,43.66
ROM0_CE  (via drill 0.51)
  Top 0.203: v33.81,13.33 30,17.14 30,17.94 30.16,18.1 30.16,23.18 32.86,23.18 IC1.22 | v37.94,47.94 37.94,49.37 37.94,50.64 31.59,50.64 31.59,49.85 CON2.20
  Bottom 0.203: v33.81,13.33 34.93,11.75 68.42,11.75 72.39,16.19 72.55,40.8 | v37.94,47.94 37.94,45.56 68.9,45.56 72.55,42.39 72.55,40.8 | 72.55,40.8
ROM1_CE  (via drill 0.51)
  Top 0.203: v16.35,23.18 17.3,23.18 IC2.22 | v44.61,23.97 43.97,24.61 43.97,36.99 v39.53,41.43 | v15.88,41.91 12.54,41.91 12.54,47.78 11.27,49.21 CON2.4
  Bottom 0.203: v16.35,23.18 16.83,23.49 25.88,23.49 26.19,23.81 28.89,23.81 29.21,23.49 42.39,23.49 42.86,23.97 v44.61,23.97 | v39.53,41.43 39.05,41.91 v15.88,41.91
VBATT  (via drill 1.78 pad 0.51)
  Top 0.61: v72.63,48.02 72.55,47.94 72.83,47.66 D3.A
  Bottom 0.61: CON2.49 CON2.50 | CON2.50 69.68,49.2 69.69,49.21 | 72.71,47.94 v72.63,48.02 71.48,49.17 CON2.50
VCC  (via drill 0.51, 0.61)
  Top 0.203: CON1.48 67.31,2.86 67.31,4.13 CON1.47 67.31,5.4 67.31,8.1 67.31,36.83 | 67.31,36.83 | 13.97,37.78 C1.1 14.61,39.37 | 13.97,35.24 IC2.32 14.13,33.18 13.97,33.18 13.97,31.75 v15.72,31.75 | 29.53,39.37 C2.1 | v28.89,31.59 28.89,32.7 29.37,33.18 IC1.32
  Top 0.254: v64.93,36.51 67.31,36.83 | Q1.1 v71.28,8.1 | 67.31,8.1 v66.67,8.1 | Q2.1 49.21,10.32 v49.21,9.37
  Top 0.406: 63.18,42.7 62.55,42.7 62.55,36.67 v62.39,36.51
  Top 0.508: CON2.40 56.99,49.85 56.99,50.64 53.18,50.64 53.18,49.69 53.18,49.53 53.18,44.13 | CON2.46 64.61,47.94 65.88,47.94 65.88,45.4 63.18,45.4 63.18,42.7 | v49.53,40.32 49.53,40.48 | v49.53,40.32
  Top 0.61: 13.97,35.24 13.97,37.78 | v29.53,40.32 29.53,39.37 | 14.61,39.37 v15.56,40.16 | 53.18,44.13 53.66,42.86 v53.66,40.32 | v53.66,40.32 | 63.18,42.7 | 63.18,42.7 D1.A
  Bottom 0.203: v28.89,31.59 28.58,31.91 20.8,31.91 20.64,31.75 v15.72,31.75 | CON2.40 56.99,49.37 | 64.61,49.37 CON2.46 | v29.53,40.32 29.85,40
  Bottom 0.254: v71.28,8.1 v66.67,8.1 63.66,8.1 62.07,9.68 55.4,9.68 54.45,8.73 53.98,8.73 52.86,9.84 49.69,9.84 v49.21,9.37
  Bottom 0.406: v62.39,36.51 v64.93,36.51
  Bottom 0.508: 56.99,49.37 56.99,47.94 64.61,47.94 | v15.56,40.16 17.94,40.16 18.1,40.48 27.15,40.48 27.38,40.24 | 27.38,40.24 | 27.38,40.24 27.54,40.08 29.29,40.08 29.53,40.4
  Bottom 0.61: 64.61,47.94 64.61,49.37 | 49.69,40.32 v53.66,40.32 | 49.69,40.32 v49.53,40.32 | v49.53,40.32 | 49.69,40.32 49.53,40.16 49.53,39.53 32.23,39.53 31.51,40.16 29.77,40.16 29.37,40.32 | 29.37,40.32 | 29.37,40.32 v29.53,40.32 29.53,40.4
  pour Top (isolate 0.305): 5.72,45.08 74.45,44.93 74.14,6.51 4.92,6.83 5.4,45.08
VCC_RAM  (via drill 0.51, 0.51 pad 0.51, 0.61)
  Top 0.203: U$1.32 53.18,36.35 | 52.71,37.23 52.7,37.23 52.7,36.04 v51.59,36.04 | v48.42,36.04 48.58,36.04 49.37,36.83 49.37,38.42 | 49.37,38.42 | 49.37,38.42 C4.1
  Top 0.254: v69.69,10.16 69.69,10 | R2.1 53.02,11.35 54.21,10.16 v54.13,10.16 | v69.69,36.04 70.09,36.04 | v66.36,10.16 v66.36,35.88
  Top 0.406: 69.69,10 v69.69,10.16 69.69,11.83 R1.1
  Top 0.508: v68.9,40.32 | v68.9,40.32 | v68.9,40.32 66.83,40.32 | U$3.32 71.6,36.06 71.6,36.04 71.52,36.04
  Top 0.61: 71.52,36.06 71.52,36.04 70.09,36.04 70.09,40.32 v68.9,40.32 | U$1.32 52.71,36.1 52.71,37.23 54.85,37.23 v54.85,42.78 | 68.74,42.7 D3.C | 68.74,42.7 D1.C 66.83,42.7 66.83,40.32 66.83,38.73 C3.1 | 68.74,42.7
  Bottom 0.203: v51.59,36.04 v48.42,36.04
  Bottom 0.254: v54.13,10.16 v66.36,10.16 | v66.36,10.16 v69.69,10.16 | v69.69,36.04 66.52,36.04 v66.36,35.88 | v66.36,10.16
  Bottom 0.61: v54.85,42.78 62.39,42.78 62.39,39.53 66.28,39.53 67.07,40.32 v68.9,40.32
WE  (via drill 0.51)
  Top 0.203: v56.04,32.38 55.25,32.38 U$1.29 53.18,32.38 51.12,32.38 49.85,32.38 49.85,36.51 51.12,37.62 v51.12,42.86 | v69.85,32.38 70.64,32.38 U$3.29 | v15.4,36.91 15.4,35.24 IC2.31 | IC1.31 30.96,35.24 30.96,37.62 v31.12,37.78 32.86,39.37 v32.86,43.5 32.86,47.94 34.13,49.21 CON2.22 | v51.12,42.86
  Bottom 0.203: v56.04,32.38 v69.85,32.38 | v15.4,36.91 15.4,37.78 23.65,37.78 23.97,37.46 30.8,37.46 v31.12,37.78 | v51.12,42.86 40.16,42.86 40.01,42.86 32.86,42.86 v32.86,43.5
(copper drawn outside any net)
  shapes: Bottom area x2, Top area x4

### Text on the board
Top: MEMORY-PCB
tStop: MEMORY-PCB
bStop: Greetings to all ATARI Users of the World! | BATT | BATT | have you played ATARI today???
Silkscreen WF: special thanks to B.Engl, HIAS, mega-hz, TFHH, W.Burger and the ABBUC! | ... and my sweet Sabine for soldering the whole lot of parts! | 50 | 2 | 1 | Expansion-Connector | 49 | 100nF | 100nF | 100nF | 100nF | A9 | 1 | 1 | 1 | 1 | Software & Logic: HIASSOFT | Hardware & Layout:MEGA-HZ | 29F040 | 29F040 | 512K SRAM | 512K SRAM | ABBUC FREEZER 2011 | 12K | BSS | PCB Vers. 4.1 | BSS | 12K | 138 | PBI-Connector | 138 | 49 | 1 | 2 | 50
SilkscreenWF LS: 3.6V Battery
